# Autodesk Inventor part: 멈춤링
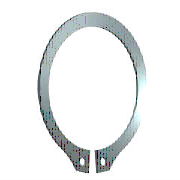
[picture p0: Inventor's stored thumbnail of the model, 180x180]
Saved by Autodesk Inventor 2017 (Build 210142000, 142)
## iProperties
IsCustomPart: 1
Created: 2012-02
Part Number: 멈춤링
Material: 강철, 연강
Description: 리테이닝 링(C형)
Document SubType Name: Modeling
Standard: KS B 1336
Designer: mduedu
Standards Organization: KS
Language: ko-KR
Size Designation: 20 x 1.2
Categories: <MemberInstance><Categories><Category DisplayName="샤프트 부품" InternalName="7f7aeb1f-a693-4053-b835-cee3144e0d98" Mnemonic="SHFT"><Category DisplayName="써클립" Inter
Density: 7.85 g/cm^3
Appearance: 노란색
Mass: 1.66335 g
Surface Area: 5.4075 cm^2
Volume: 0.211892 cm^3
Author: mduedu
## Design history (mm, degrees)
sketch "스케치1"
  geometry: L1 (-6, 0)-(6, 0) reference; L2 (0, 20.189)-(0, -80.536) reference; L3 (-48.09, 0)-(48.09, 0) reference; L4 (-0.5, -19.487)-(-0.5, -23.387); L5 (-0.5, -6.54)-(-0.5, -13.29); L6 (-2.795, 2.7)-(3.672, 2.7); L7 (0.5, -6.54)-(0.5, -13.29); L8 (0.5, -19.487)-(0.5, -23.387); C1 r 1 at (-2, -21.219); C2 r 1 at (2, -21.219); A1 r 9.5 centre (0, -10) between (0.5, -19.487) and (-0.5, -19.487); A2 r 12.025 centre (0, -9.325) between (5.071, -20.228) and (-5.071, -20.228); A3 r 13.396 centre (0, -10) between (-2.351, -23.188) and (-0.5, -23.387); A4 r 2 centre (-2, -21.219) between (-3.957, -21.631) and (-2.351, -23.188); A5 r 2 centre (-5.915, -22.042) between (-3.957, -21.631) and (-5.071, -20.228); A6 r 2 centre (5.915, -22.042) between (5.071, -20.228) and (3.957, -21.631); A7 r 2 centre (2, -21.219) between (2.351, -23.188) and (3.957, -21.631); A8 r 13.396 centre (0, -10) between (0.5, -23.387) and (2.351, -23.188)
  constraints: 16 point on circle, 12 end point, 10 centre point, 9 symmetric about line, 5 point on line, 4 tangent, 3 coincident, 2 horizontal, 1 perpendicular, 1 vertical, 5 other
  dimensions: "d0" = 19 diameter of A1 (= ND); "d1" = 3.9 distance of L4.end L4.start (= SRB2); "d6" = 0.5 distance between parallel lines of L2 L5 (= 0.25 x SD5); "d7" = 2.7 distance between parallel lines of L6 L3 (= SRB1); "d8" = 0.675 distance of A1.centre A2.centre (= 0.25 x SRB1); "d9" = 2 radius of A4 (= SD5); "d10" = 2 radius of A5 (= SD5); "d11" = 1.5 distance from line of L4 A4.centre (= 0.75 x SD5); "d12" = 2 diameter of C1 (= SD5); "d13" = 2 diameter of C2 (= SD5); "d14" = 10 distance from line of A1.centre L1 (= 0.5 x WD)
extrude "본체" new body sketch "스케치1" distance "d2" = 1.2 (= SD); taper "d3" = 0 deg
workaxis "Work Axis1"
workplane "Work Plane1"
body "Solid1"
other parameters: "SD" = 1.2 [user parameter; used in 1 equation term], "SRB1" = 2.7 [user parameter; used in 2 equation terms], "ND" = 19 [user parameter; used in 1 equation term], "SRB2" = 3.9 [user parameter; used in 1 equation term], "SD5" = 2 [user parameter; used in 6 equation terms], "d15" = 0, "d16" = 0, "d17" = 0, "d41" = 0, "d42" = 0, "SD3" = 18.5 [user parameter], "WDMAX" = 21 [user parameter]
